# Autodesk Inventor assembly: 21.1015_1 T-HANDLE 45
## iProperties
Created: 2007-03
Part Number: 21.1015_1 T-HANDLE 45
Document SubType Name: Assembly
Designer: Andy Moles
Translation Standard: STEP AP214IS
File Name: 1000-U641_ASM
Preprocessor: PRO/ENGINEER BY PARAMETRIC TECHNOLOGY CORPORATION, 2003200
Postprocessor: Build: 344b, Release: 11 SP2 - Date: Fri 08/18/2006
Sent Units: MILLIMETERS
Uncertainty: 0.01136958734563
Author: Andy Moles
